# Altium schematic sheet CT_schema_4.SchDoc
size 283 x 147 mm
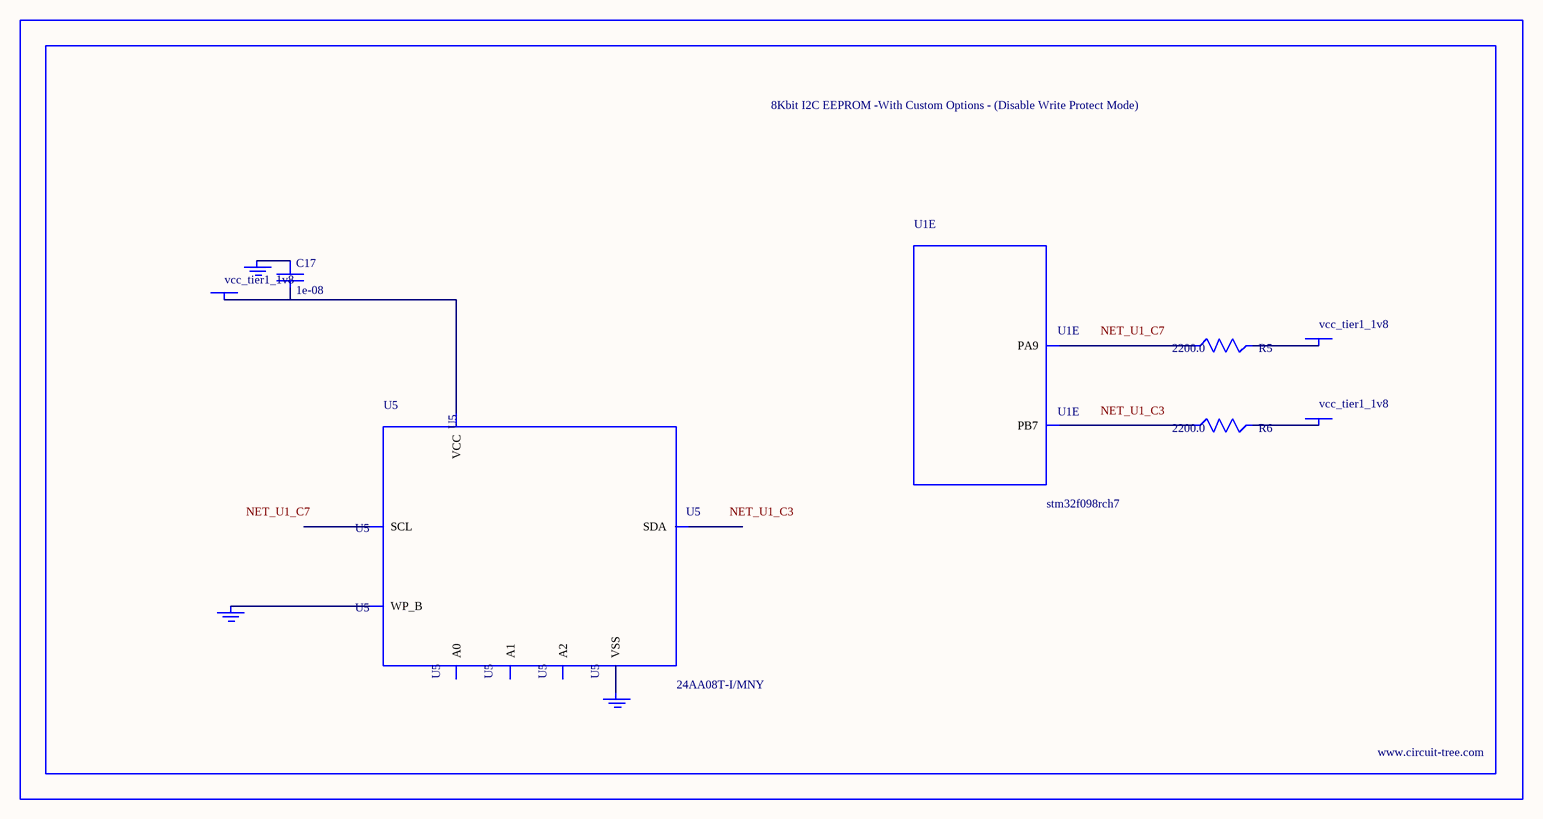
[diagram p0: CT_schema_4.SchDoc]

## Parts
BORDER3  (no value)
C17  1e-08  [C0402]
GND_INSTANCE_3_0  (no value)
GND_INSTANCE_3_1  (no value)
GND_INSTANCE_3_2  (no value)
POWER_INSTANCE_3_0  vcc_tier1_1v8
POWER_INSTANCE_3_1  vcc_tier1_1v8
POWER_INSTANCE_3_2  vcc_tier1_1v8
R5  2200.0  [R0603]
R6  2200.0  [R0603]
U1  stm32f098rch7  [UFBGA64]  (part E of 6)
U5  24AA08T-I/MNY  [TDFN-8/6MM]

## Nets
NetC17_1: C17.1 GND_INSTANCE_3_1.0(GND)
NetC17_2: C17.2 POWER_INSTANCE_3_0.0(PWR) U5.8(VCC)
NetGND_INSTANCE_3_0_0: GND_INSTANCE_3_0.0(GND) U5.7(WP_B)
NetGND_INSTANCE_3_2_0: GND_INSTANCE_3_2.0(GND) U5.4(VSS)
NetPOWER_INSTANCE_3_1_0: POWER_INSTANCE_3_1.0(PWR) R5.2
NetPOWER_INSTANCE_3_2_0: POWER_INSTANCE_3_2.0(PWR) R6.2
NetR5_1: R5.1 U1.C7(PA9)
NetR6_1: R6.1 U1.C3(PB7)

Not connected (* = marked no-connect by the designer): U5 1(A0) 2(A1) 3(A2) 5(SDA) 6(SCL)

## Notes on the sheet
- Labels drawn without touching a wire or pin: NET_U1_C3, NET_U1_C7

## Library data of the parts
BORDER3 = BORDER_PAGE3
C17 = C0402C103K3RAC
GND_INSTANCE_3_0-GND_INSTANCE_3_2 = GND
POWER_INSTANCE_3_0-POWER_INSTANCE_3_2 = PWR
R5 R6 = RC0603JR-072K2L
